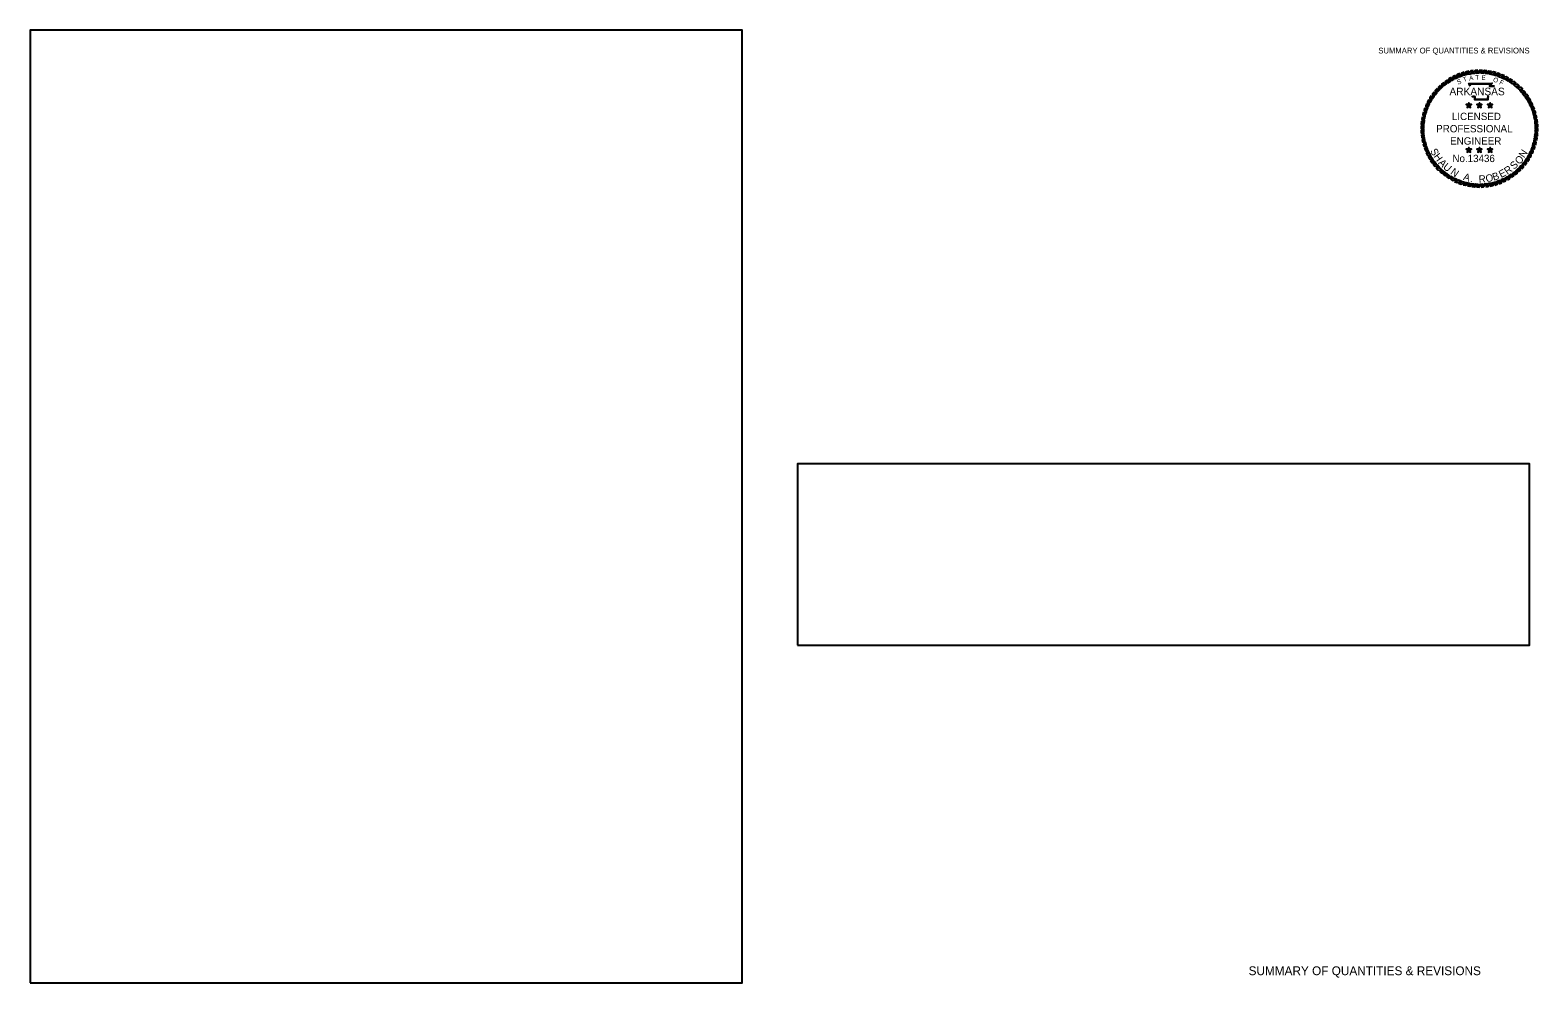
# Model space of a CAD drawing. Extents: x 762409 to 765490, y 1659571 to 1661518.
import ezdxf

# ---------------------------------------------------------------- set-up
doc = ezdxf.new("R2010")
doc.units = 0
for name, color, linetype in [('1', 7, 'Continuous'), ('60', 7, 'Continuous'), ('G-ANNO-SYMB', 7, 'Continuous')]:
    doc.layers.add(name, color=color, linetype=linetype)

msp = doc.modelspace()

# ---------------------------------------------------------------- linework, layer by layer
at = {"layer": '1'}
for points in [[(762409, 1659571), (763864.2, 1659571), (763864.2, 1661517.9), (762409, 1661517.9)], [(763977.5, 1660261.1), (765473.3, 1660261.1), (765473.3, 1660631.9), (763977.5, 1660631.9)]]:
    msp.add_lwpolyline(points, close=True, dxfattribs=at)
at = {"layer": 'G-ANNO-SYMB'}
for points in [[(765340, 1661431.8), (765335, 1661430.3), (765329.9, 1661422.8), (765335.1, 1661424.6)], [(765349.1, 1661433.9), (765344.1, 1661432.8), (765338.4, 1661425.7), (765343.7, 1661427.1)], [(765358.4, 1661435.3), (765353.3, 1661434.6), (765347, 1661427.9), (765352.5, 1661428.9)], [(765367.7, 1661435.9), (765362.6, 1661435.6), (765355.8, 1661429.5), (765361.4, 1661430.1)], [(765377.1, 1661435.8), (765372, 1661435.9), (765364.7, 1661430.3), (765370.3, 1661430.5)], [(765386.4, 1661435), (765381.3, 1661435.5), (765373.7, 1661430.5), (765379.2, 1661430.2)], [(765395.7, 1661433.4), (765390.6, 1661434.3), (765382.6, 1661429.9), (765388.1, 1661429.2)], [(765404.7, 1661431.1), (765399.8, 1661432.4), (765391.5, 1661428.6), (765396.9, 1661427.5)], [(765291.1, 1661405.1), (765287.3, 1661401.6), (765286.2, 1661392.5), (765290, 1661396.5)], [(765298.3, 1661411.1), (765294.3, 1661407.9), (765292.4, 1661398.9), (765296.5, 1661402.7)], [(765305.9, 1661416.5), (765301.7, 1661413.6), (765299.1, 1661404.8), (765303.5, 1661408.2)], [(765313.9, 1661421.3), (765309.5, 1661418.8), (765306.3, 1661410.2), (765310.9, 1661413.3)], [(765322.3, 1661425.5), (765317.7, 1661423.3), (765313.8, 1661415), (765318.7, 1661417.7)], [(765331, 1661429), (765326.2, 1661427.2), (765321.7, 1661419.2), (765326.8, 1661421.5)], [(765413.6, 1661428.1), (765408.8, 1661429.8), (765400.2, 1661426.7), (765405.5, 1661425.2)], [(765422.2, 1661424.4), (765417.6, 1661426.5), (765408.7, 1661424.1), (765413.9, 1661422.1)], [(765430.5, 1661420.1), (765426, 1661422.6), (765417.1, 1661420.8), (765422.1, 1661418.4)], [(765438.5, 1661415.1), (765434.2, 1661417.9), (765425.1, 1661416.9), (765429.9, 1661414.1)], [(765446, 1661409.5), (765441.9, 1661412.7), (765432.8, 1661412.3), (765437.4, 1661409.2)], [(765453, 1661403.4), (765449.2, 1661406.8), (765440.1, 1661407.2), (765444.4, 1661403.7)], [(765459.6, 1661396.7), (765456.1, 1661400.4), (765447, 1661401.5), (765451, 1661397.7)], [(765267.6, 1661376), (765265.2, 1661371.5), (765266.9, 1661362.5), (765269.3, 1661367.6)], [(765272.6, 1661384), (765269.8, 1661379.7), (765270.9, 1661370.6), (765273.6, 1661375.4)], [(765278.2, 1661391.5), (765275.1, 1661387.4), (765275.4, 1661378.3), (765278.5, 1661382.9)], [(765284.4, 1661398.5), (765280.9, 1661394.7), (765280.5, 1661385.6), (765284, 1661389.9)], [(765349.3, 1661364.1), (765350.5, 1661365.8), (765349.3, 1661369.6), (765348.1, 1661365.8)], [(765371.1, 1661364.1), (765372.3, 1661365.8), (765371.1, 1661369.6), (765369.9, 1661365.8)], [(765392.9, 1661364.1), (765394.2, 1661365.8), (765392.9, 1661369.6), (765391.7, 1661365.8)], [(765465.6, 1661389.5), (765462.4, 1661393.5), (765453.4, 1661395.3), (765457.2, 1661391.2)], [(765471, 1661381.8), (765468.1, 1661386.1), (765459.3, 1661388.6), (765462.7, 1661384.2)], [(765475.8, 1661373.8), (765473.3, 1661378.3), (765464.7, 1661381.5), (765467.8, 1661376.8)], [(765480, 1661365.4), (765477.8, 1661370), (765469.5, 1661373.9), (765472.2, 1661369.1)], [(765254.4, 1661341.1), (765253.4, 1661336.1), (765257.8, 1661328.1), (765258.5, 1661333.6)], [(765256.6, 1661350.2), (765255.3, 1661345.3), (765259.1, 1661337), (765260.2, 1661342.4)], [(765259.6, 1661359.1), (765257.9, 1661354.3), (765261, 1661345.7), (765262.6, 1661351)], [(765263.3, 1661367.7), (765261.2, 1661363), (765263.7, 1661354.2), (765265.6, 1661359.4)], [(765349.3, 1661364.1), (765348.1, 1661365.8), (765344.1, 1661365.8), (765347.3, 1661363.5)], [(765349.3, 1661364.1), (765347.3, 1661363.5), (765346.1, 1661359.7), (765349.3, 1661362)], [(765349.3, 1661364.1), (765351.3, 1661363.5), (765354.5, 1661365.8), (765350.5, 1661365.8)], [(765349.3, 1661364.1), (765349.3, 1661362), (765352.5, 1661359.7), (765351.3, 1661363.5)], [(765371.1, 1661364.1), (765369.9, 1661365.8), (765365.9, 1661365.8), (765369.1, 1661363.5)], [(765371.1, 1661364.1), (765369.1, 1661363.5), (765367.9, 1661359.7), (765371.1, 1661362)], [(765371.1, 1661364.1), (765373.1, 1661363.5), (765376.3, 1661365.8), (765372.3, 1661365.8)], [(765371.1, 1661364.1), (765371.1, 1661362), (765374.3, 1661359.7), (765373.1, 1661363.5)], [(765392.9, 1661364.1), (765391.7, 1661365.8), (765387.8, 1661365.8), (765391, 1661363.5)], [(765392.9, 1661364.1), (765391, 1661363.5), (765389.7, 1661359.7), (765392.9, 1661362)], [(765392.9, 1661364.1), (765394.9, 1661363.5), (765398.1, 1661365.8), (765394.2, 1661365.8)], [(765392.9, 1661364.1), (765392.9, 1661362), (765396.1, 1661359.7), (765394.9, 1661363.5)], [(765483.5, 1661356.7), (765481.7, 1661361.5), (765473.7, 1661366), (765476, 1661361)], [(765486.3, 1661347.8), (765484.9, 1661352.7), (765477.3, 1661357.8), (765479.2, 1661352.6)], [(765488.4, 1661338.6), (765487.3, 1661343.7), (765480.2, 1661349.4), (765481.6, 1661344)], [(765489.8, 1661329.4), (765489.1, 1661334.5), (765482.4, 1661340.7), (765483.5, 1661335.3)], [(765252, 1661322.6), (765251.8, 1661317.4), (765257.4, 1661310.2), (765257.3, 1661315.8)], [(765251.9, 1661313.2), (765252.1, 1661308.1), (765258.3, 1661301.3), (765257.7, 1661306.8)], [(765252.8, 1661331.9), (765252.2, 1661326.8), (765257.3, 1661319.2), (765257.5, 1661324.7)], [(765490.4, 1661320), (765490.1, 1661325.2), (765484, 1661331.9), (765484.6, 1661326.4)], [(765489.5, 1661301.3), (765490, 1661306.4), (765485, 1661314.1), (765484.7, 1661308.5)], [(765490.3, 1661310.7), (765490.4, 1661315.8), (765484.8, 1661323), (765485, 1661317.5)], [(765252.5, 1661303.9), (765253.1, 1661298.8), (765259.8, 1661292.5), (765258.8, 1661298)], [(765253.9, 1661294.6), (765254.9, 1661289.6), (765262.1, 1661283.9), (765260.6, 1661289.2)], [(765255.9, 1661285.5), (765257.4, 1661280.5), (765265, 1661275.4), (765263.1, 1661280.6)], [(765258.7, 1661276.5), (765260.6, 1661271.7), (765268.5, 1661267.2), (765266.2, 1661272.3)], [(765349.3, 1661272.8), (765350.5, 1661274.5), (765349.3, 1661278.2), (765348.1, 1661274.5)], [(765371.1, 1661272.8), (765372.3, 1661274.5), (765371.1, 1661278.2), (765369.9, 1661274.5)], [(765392.9, 1661272.8), (765394.2, 1661274.5), (765392.9, 1661278.2), (765391.7, 1661274.5)], [(765478.9, 1661265.5), (765481, 1661270.2), (765478.6, 1661279), (765476.6, 1661273.8)], [(765482.6, 1661274.1), (765484.3, 1661279), (765481.2, 1661287.6), (765479.7, 1661282.2)], [(765485.6, 1661283), (765486.9, 1661288), (765483.2, 1661296.3), (765482, 1661290.8)], [(765487.9, 1661292.1), (765488.8, 1661297.1), (765484.4, 1661305.1), (765483.7, 1661299.6)], [(765262.2, 1661267.8), (765264.4, 1661263.2), (765272.7, 1661259.3), (765270.1, 1661264.2)], [(765266.4, 1661259.4), (765269, 1661255), (765277.5, 1661251.8), (765274.5, 1661256.4)], [(765271.2, 1661251.4), (765274.1, 1661247.2), (765282.9, 1661244.6), (765279.5, 1661249)], [(765349.3, 1661272.8), (765348.1, 1661274.5), (765344.1, 1661274.5), (765347.3, 1661272.1)], [(765349.3, 1661272.8), (765347.3, 1661272.1), (765346.1, 1661268.4), (765349.3, 1661270.7)], [(765349.3, 1661272.8), (765351.3, 1661272.1), (765354.5, 1661274.5), (765350.5, 1661274.5)], [(765349.3, 1661272.8), (765349.3, 1661270.7), (765352.5, 1661268.4), (765351.3, 1661272.1)], [(765371.1, 1661272.8), (765369.9, 1661274.5), (765365.9, 1661274.5), (765369.1, 1661272.1)], [(765371.1, 1661272.8), (765369.1, 1661272.1), (765367.9, 1661268.4), (765371.1, 1661270.7)], [(765371.1, 1661272.8), (765373.1, 1661272.1), (765376.3, 1661274.5), (765372.3, 1661274.5)], [(765371.1, 1661272.8), (765371.1, 1661270.7), (765374.3, 1661268.4), (765373.1, 1661272.1)], [(765392.9, 1661272.8), (765391.7, 1661274.5), (765387.8, 1661274.5), (765391, 1661272.1)], [(765392.9, 1661272.8), (765391, 1661272.1), (765389.7, 1661268.4), (765392.9, 1661270.7)], [(765392.9, 1661272.8), (765394.9, 1661272.1), (765398.1, 1661274.5), (765394.2, 1661274.5)], [(765392.9, 1661272.8), (765392.9, 1661270.7), (765396.1, 1661268.4), (765394.9, 1661272.1)], [(765457.9, 1661234.7), (765461.3, 1661238.5), (765461.7, 1661247.6), (765458.2, 1661243.3)], [(765464, 1661241.7), (765467.2, 1661245.8), (765466.8, 1661255), (765463.7, 1661250.4)], [(765469.6, 1661249.3), (765472.4, 1661253.6), (765471.4, 1661262.7), (765468.6, 1661257.8)], [(765474.6, 1661257.2), (765477.1, 1661261.7), (765475.3, 1661270.7), (765473, 1661265.7)], [(765276.6, 1661243.8), (765279.9, 1661239.8), (765288.8, 1661237.9), (765285.1, 1661242)], [(765282.6, 1661236.6), (765286.2, 1661232.8), (765295.2, 1661231.7), (765291.2, 1661235.5)], [(765289.2, 1661229.9), (765293, 1661226.4), (765302.1, 1661226), (765297.8, 1661229.5)], [(765296.3, 1661223.7), (765300.3, 1661220.6), (765309.5, 1661220.9), (765304.9, 1661224)], [(765303.8, 1661218.1), (765308.1, 1661215.3), (765317.2, 1661216.4), (765312.3, 1661219.1)], [(765311.7, 1661213.1), (765316.2, 1661210.7), (765325.2, 1661212.4), (765320.2, 1661214.8)], [(765419.9, 1661207.7), (765424.6, 1661209.9), (765428.4, 1661218.2), (765423.6, 1661215.5)], [(765428.3, 1661211.9), (765432.8, 1661214.4), (765436, 1661223), (765431.3, 1661220)], [(765436.3, 1661216.7), (765440.6, 1661219.6), (765443.1, 1661228.4), (765438.7, 1661225)], [(765444, 1661222.1), (765448, 1661225.3), (765449.8, 1661234.3), (765445.7, 1661230.6)], [(765451.2, 1661228.1), (765454.9, 1661231.7), (765456, 1661240.7), (765452.2, 1661236.7)], [(765320, 1661208.8), (765324.7, 1661206.7), (765333.5, 1661209.1), (765328.3, 1661211.1)], [(765328.6, 1661205.1), (765333.5, 1661203.4), (765342.1, 1661206.5), (765336.7, 1661208.1)], [(765337.5, 1661202.1), (765342.5, 1661200.8), (765350.8, 1661204.6), (765345.4, 1661205.7)], [(765346.6, 1661199.8), (765351.6, 1661198.9), (765359.6, 1661203.3), (765354.1, 1661204)], [(765355.8, 1661198.3), (765360.9, 1661197.7), (765368.6, 1661202.8), (765363, 1661203)], [(765365.2, 1661197.4), (765370.3, 1661197.3), (765377.5, 1661202.9), (765372, 1661202.8)], [(765374.5, 1661197.3), (765379.7, 1661197.6), (765386.4, 1661203.8), (765380.9, 1661203.2)], [(765383.9, 1661198), (765389, 1661198.6), (765395.2, 1661205.3), (765389.8, 1661204.3)], [(765393.1, 1661199.3), (765398.2, 1661200.4), (765403.9, 1661207.6), (765398.5, 1661206.1)], [(765402.3, 1661201.4), (765407.2, 1661202.9), (765412.3, 1661210.5), (765407.1, 1661208.6)], [(765411.2, 1661204.2), (765416, 1661206.1), (765420.5, 1661214), (765415.5, 1661211.7)]]:
    msp.add_lwpolyline(points, close=True, dxfattribs=at)
for points in [[(765352, 1661403.2), (765349.2, 1661409.2), (765397.4, 1661409.3), (765393.3, 1661404.2), (765396.6, 1661404.3), (765399.3, 1661404.3), (765402.1, 1661404)], [(765352.7, 1661403.5), (765350.4, 1661408.5), (765395.8, 1661408.5), (765391.7, 1661403.4), (765396.6, 1661403.5), (765399.3, 1661403.5), (765402, 1661403.2)], [(765389.8, 1661383), (765388.9, 1661382.4), (765388.7, 1661381.4), (765388.4, 1661378.9), (765388.4, 1661375.6), (765361.5, 1661375.6), (765361.5, 1661380.1), (765361.5, 1661381), (765360.4, 1661381.4), (765356.6, 1661381.4), (765355.9, 1661382.4)], [(765389.3, 1661383.6), (765388.3, 1661382.8), (765387.9, 1661381.5), (765387.6, 1661378.9), (765387.6, 1661376.3), (765362.3, 1661376.3), (765362.3, 1661380.1), (765362.3, 1661381.6), (765360.6, 1661382.1), (765357, 1661382.1), (765356.6, 1661382.8)]]:
    msp.add_lwpolyline(points, dxfattribs=at)

# ---------------------------------------------------------------- texts
at = {"layer": '1'}
msp.add_text('SUMMARY OF QUANTITIES & REVISIONS', height=11.724, rotation=360, dxfattribs=at).set_placement((765164.4, 1661470.3))
at = {"layer": '60'}
msp.add_text('SUMMARY OF QUANTITIES & REVISIONS', height=18, rotation=360, dxfattribs=at).set_placement((764899.3, 1659586.7))
at = {"layer": 'G-ANNO-SYMB'}
for s, height, rotation, p in [('ARKANSAS', 15.49, 360, (765309.9, 1661384.8)), ('S', 9.49, 19.7726, (765326.9, 1661406.4)), ('T', 9.49, 16.9015, (765339, 1661411.8)), ('A', 9.49, 8.6788, (765350.5, 1661414.8)), ('T', 9.49, 1.4789, (765362.8, 1661416.7)), ('E', 9.49, 356.672, (765374.9, 1661416.4)), ('O', 9.49, 341.2218, (765398, 1661413.1)), ('F', 9.49, 335.3628, (765410.8, 1661408.1)), ('LICENSED', 15, 360, (765314.7, 1661334.2)), ('PROFESSIONAL', 15, 360, (765282.6, 1661309.1)), ('S', 15, 298.1636, (765269.8, 1661271.4)), ('ENGINEER', 15, 360, (765311.1, 1661284)), ('H', 15, 305.619, (765276.6, 1661259.7)), ('A', 15, 313.4472, (765286.1, 1661246)), ('U', 15, 320.9026, (765295.5, 1661236.2)), ('No.13436', 14.94, 360, (765315.9, 1661248.3)), ('S', 15, 43.4878, (765441.9, 1661232.3)), ('O', 15, 44.7757, (765452.2, 1661242.2)), ('N', 15, 56.1007, (765462.6, 1661255.7)), ('N', 15, 324.9326, (765310.6, 1661225)), ('A', 15, 343.0991, (765336.7, 1661212.2)), ('R', 15, 3.2287, (765369.9, 1661205.9)), ('O', 15, 11.4296, (765385.2, 1661206.9)), ('B', 15, 18.885, (765400.3, 1661210)), ('E', 15, 27.8315, (765415.4, 1661215.5)), ('R', 15, 35.6597, (765428.1, 1661222.1)), ('.', 15, 351.3, (765351.5, 1661207.8))]:
    msp.add_text(s, height=height, rotation=rotation, dxfattribs=at).set_placement(p)

doc.saveas('drawing.dxf')
